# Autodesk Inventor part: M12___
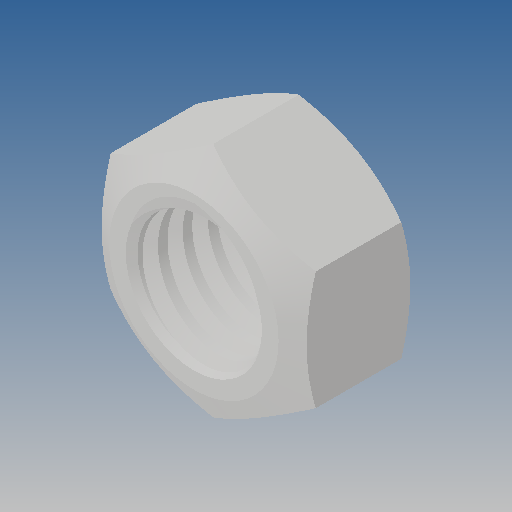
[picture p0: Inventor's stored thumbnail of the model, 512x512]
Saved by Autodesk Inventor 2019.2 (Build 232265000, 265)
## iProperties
Created: 2010-06
Part Number: M12___
Material: Ogólny
Document SubType Name: Modeling
Designer: CADENGINEERING4
Density: 1 g/cm^3
Appearance: Domyślna
Author: CADENGINEERING4
Revision Number: ANY
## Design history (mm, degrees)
feature "NONE"
node "Bryła1"
